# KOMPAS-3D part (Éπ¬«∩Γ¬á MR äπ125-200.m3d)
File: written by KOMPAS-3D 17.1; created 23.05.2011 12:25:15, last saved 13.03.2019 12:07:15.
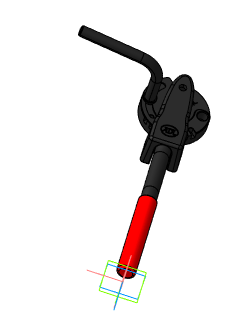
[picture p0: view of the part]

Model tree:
1. Плоскость XY
2. Плоскость ZX
3. Плоскость ZY
4. Ось X
5. Ось Y
6. Ось Z
7. Начало координат
8. Операция без истории:3

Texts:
  Viktor2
